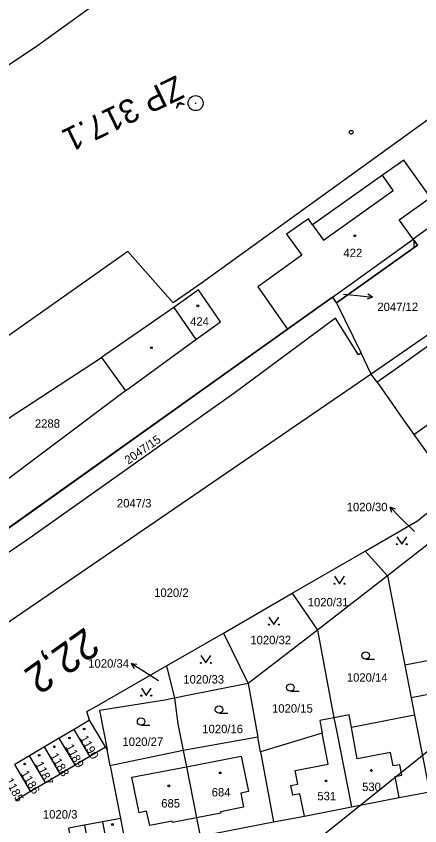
# Model space of a CAD drawing. Extents: x -793666 to -785424, y -1118958 to -1108761.
# Drawn here: x -792219.4 to -792138.1, y -1109916.5 to -1109753.4 of the extents above; entities that cross this region are included whole.
import ezdxf

# ---------------------------------------------------------------- set-up
doc = ezdxf.new("R2010")
doc.units = 0
for name, color, linetype in [('1', 7, 'Continuous'), ('1_2000 - úřady', 7, 'Continuous'), ('Hranice parcel', 7, 'Continuous'), ('Parcelní čísla', 7, 'Continuous'), ('Pop  PČ popisy', 7, 'Continuous'), ('Vnitřní kresba', 7, 'Continuous'), ('Vrstva 44', 7, 'Continuous'), ('Vrstva 53', 7, 'Continuous'), ('Vrstva 63', 7, 'Continuous'), ('Vrstva 7', 7, 'Continuous'), ('Značky budov', 7, 'Continuous'), ('Značky kultur', 7, 'Continuous')]:
    doc.layers.add(name, color=color, linetype=linetype)

msp = doc.modelspace()

# ---------------------------------------------------------------- linework, layer by layer
at = {"layer": '1'}
for q in [(-792262.89, -1109847.12), (-792187.76, -1109811.11)]:
    msp.add_line((-792196.9, -1109800.79), q, dxfattribs=at)
for points in [[(-792036.03, -1109711.9), (-792041.12, -1109704.75), (-792068.33, -1109725.02), (-792101.91, -1109749.26), (-792182.09, -1109807.15)], [(-792182.09, -1109807.15), (-792187.76, -1109811.11)]]:
    msp.add_lwpolyline(points, dxfattribs=at)
msp.add_circle((-792151.91, -1109776.75), 0.375, dxfattribs=at)
at = {"layer": '1_2000 - úřady'}
msp.add_lwpolyline([(-791938.08, -1109742.36), (-792598.01, -1110271.46), (-792786.15, -1110036.8), (-792126.22, -1109507.7)], close=True, dxfattribs=at)
at = {"layer": 'Hranice parcel'}
for p, q in [((-792164.73, -1109816.44), (-792155.68, -1109810)), ((-792155.68, -1109810), (-792154.86, -1109811.14)), ((-792154.86, -1109811.14), (-792149.91, -1109821.24)), ((-792246.55, -1109874.61), (-792164.73, -1109816.44)), ((-792147.85, -1109825.45), (-792149.91, -1109821.24)), ((-792202.2, -1109822.1), (-792197.4, -1109828.81)), ((-792147.85, -1109825.45), (-792244.24, -1109891.34)), ((-792146.7, -1109827.09), (-792147.85, -1109825.45)), ((-792130.85, -1109855.33), (-792144.6, -1109866.13)), ((-792163.8, -1109869.62), (-792149.1, -1109861.11)), ((-792149.1, -1109861.11), (-792144.6, -1109866.13)), ((-792144.6, -1109866.13), (-792158.71, -1109877.05)), ((-792144.6, -1109866.13), (-792141.07, -1109884.12)), ((-792177.65, -1109877.63), (-792163.8, -1109869.62)), ((-792163.8, -1109869.62), (-792158.71, -1109877.05)), ((-792189.12, -1109884.23), (-792177.65, -1109877.63)), ((-792177.65, -1109877.63), (-792172.69, -1109887.78)), ((-792158.71, -1109877.05), (-792172.69, -1109887.78)), ((-792158.71, -1109877.05), (-792155.38, -1109894.7)), ((-792189.12, -1109884.23), (-792187.51, -1109890.76)), ((-792172.69, -1109887.78), (-792170.71, -1109898.62)), ((-792139.11, -1109894.16), (-792136.09, -1109909.62)), ((-792204.62, -1109895.19), (-792207.76, -1109897.06)), ((-792201.42, -1109900.59), (-792204.62, -1109895.19)), ((-792207.76, -1109897.06), (-792210.75, -1109898.83)), ((-792204.56, -1109902.45), (-792207.76, -1109897.06)), ((-792210.75, -1109898.83), (-792213.74, -1109900.59)), ((-792207.56, -1109904.22), (-792210.75, -1109898.83)), ((-792170.71, -1109898.62), (-792185.77, -1109901.33)), ((-792170.17, -1109901.6), (-792170.71, -1109898.62)), ((-792213.74, -1109900.59), (-792216.72, -1109902.36)), ((-792210.54, -1109905.99), (-792213.74, -1109900.59)), ((-792204.56, -1109902.45), (-792201.42, -1109900.59)), ((-792201.11, -1109901.1), (-792201.42, -1109900.59)), ((-792200.48, -1109904.39), (-792201.11, -1109901.1)), ((-792216.72, -1109902.36), (-792219.71, -1109904.13)), ((-792213.53, -1109907.76), (-792216.72, -1109902.36)), ((-792207.56, -1109904.22), (-792204.56, -1109902.45)), ((-792170.17, -1109901.6), (-792167.58, -1109915.69)), ((-792216.52, -1109909.52), (-792219.71, -1109904.13)), ((-792210.54, -1109905.99), (-792207.56, -1109904.22)), ((-792200.48, -1109904.39), (-792198.4, -1109914.97)), ((-792213.53, -1109907.76), (-792210.54, -1109905.99)), ((-792216.52, -1109909.52), (-792213.53, -1109907.76)), ((-792219.5, -1109911.29), (-792216.52, -1109909.52)), ((-792202.02, -1109915.66), (-792205.67, -1109916.35)), ((-792198.4, -1109914.97), (-792202.02, -1109915.66)), ((-792202.02, -1109915.66), (-792200.79, -1109922.09)), ((-792198.4, -1109914.97), (-792197.14, -1109921.4)), ((-792182.33, -1109918.59), (-792167.58, -1109915.69)), ((-792205.67, -1109916.35), (-792204.45, -1109922.79))]:
    msp.add_line(p, q, dxfattribs=at)
for points in [[(-792226.53, -1109766.83), (-792215.1, -1109759.26), (-792190.07, -1109741.13), (-792187.8, -1109739.49), (-792182.21, -1109735.57)], [(-792088.89, -1109762.3), (-792112.22, -1109778.74), (-792129.24, -1109790.96), (-792130.77, -1109792.06), (-792139.4, -1109798.31)], [(-792139.4, -1109798.31), (-792142.25, -1109794.38), (-792135.9, -1109789.9), (-792141.29, -1109782.35), (-792145.59, -1109785.4), (-792159.68, -1109795.39), (-792160.54, -1109794.19), (-792164.93, -1109797.25), (-792161.84, -1109801.51), (-792170.75, -1109807.89), (-792164.73, -1109816.44)], [(-792155.68, -1109810), (-792151.63, -1109807.06), (-792139.68, -1109798.51), (-792139.4, -1109798.31)], [(-792154.86, -1109811.14), (-792138.54, -1109799.49), (-792139.4, -1109798.31)], [(-792119.78, -1109808.18), (-792120.9, -1109806.8), (-792147.85, -1109825.45)], [(-792197.4, -1109828.81), (-792183.19, -1109818.5), (-792178.27, -1109814.93), (-792182.67, -1109808.46), (-792187.68, -1109812.04), (-792202.2, -1109822.1)], [(-792121.37, -1109809.32), (-792125.81, -1109812.22), (-792143.12, -1109824.61), (-792146.7, -1109827.09)], [(-792149.91, -1109821.24), (-792150.43, -1109821.57), (-792155.08, -1109814.18), (-792175.53, -1109829.37), (-792217.28, -1109858.93), (-792231.29, -1109868.36), (-792246.55, -1109874.61)], [(-792197.4, -1109828.81), (-792224.99, -1109849.52), (-792231.36, -1109841.16), (-792202.2, -1109822.1)], [(-792146.7, -1109827.09), (-792143.74, -1109831.31), (-792142.22, -1109833.47), (-792139.27, -1109837.66), (-792132.41, -1109847.24), (-792127.98, -1109853)], [(-792149.1, -1109861.11), (-792138.53, -1109855), (-792136.75, -1109853.52), (-792131.07, -1109855.27), (-792130.85, -1109855.33)], [(-792125.37, -1109880.3), (-792130.03, -1109881.49), (-792129.95, -1109881.94), (-792141.07, -1109884.12)], [(-792204.62, -1109895.19), (-792205.19, -1109893.47), (-792203.27, -1109892.37), (-792189.12, -1109884.23)], [(-792141.07, -1109884.12), (-792139.79, -1109890.67), (-792139.11, -1109894.16)], [(-792172.69, -1109887.78), (-792185.54, -1109890.37), (-792187.51, -1109890.76)], [(-792187.51, -1109890.76), (-792189.46, -1109891.15), (-792202.65, -1109893.23), (-792201.11, -1109901.1)], [(-792187.51, -1109890.76), (-792186.82, -1109895.94), (-792185.77, -1109901.33)], [(-792139.11, -1109894.16), (-792151.86, -1109896.66), (-792152.34, -1109894.11), (-792155.38, -1109894.7)], [(-792155.38, -1109894.7), (-792158.21, -1109895.25), (-792157.72, -1109897.8), (-792170.17, -1109901.6)], [(-792155.38, -1109894.7), (-792154.89, -1109897.3), (-792151.83, -1109912.63)], [(-792185.77, -1109901.33), (-792197.65, -1109903.78), (-792200.21, -1109904.33), (-792200.48, -1109904.39)], [(-792185.77, -1109901.33), (-792185.12, -1109904.56), (-792183.07, -1109914.88), (-792182.33, -1109918.59)], [(-792151.83, -1109912.63), (-792142.25, -1109910.79), (-792136.09, -1109909.62)], [(-792167.58, -1109915.69), (-792161.31, -1109914.51), (-792151.83, -1109912.63)], [(-792205.67, -1109916.35), (-792208.89, -1109916.96), (-792207.73, -1109923.09)]]:
    msp.add_lwpolyline(points, dxfattribs=at)
at = {"layer": 'Pop  PČ popisy'}
for p, q in [((-792153.46, -1109809.36), (-792150.62, -1109809.64)), ((-792150.62, -1109809.64), (-792147.64, -1109809.95)), ((-792147.64, -1109809.95), (-792148.58, -1109809.35)), ((-792147.64, -1109809.95), (-792148.68, -1109810.35)), ((-792142, -1109854.36), (-792144.12, -1109852.24)), ((-792144.12, -1109852.24), (-792143.06, -1109852.59)), ((-792144.12, -1109852.24), (-792143.77, -1109853.3)), ((-792139.15, -1109857.21), (-792142, -1109854.36)), ((-792193.69, -1109885.38), (-792196.23, -1109883.79)), ((-792196.23, -1109883.79), (-792195.12, -1109883.9)), ((-792196.23, -1109883.79), (-792195.65, -1109884.75)), ((-792190.75, -1109887.24), (-792193.69, -1109885.38))]:
    msp.add_line(p, q, dxfattribs=at)
at = {"layer": 'Vnitřní kresba'}
for p, q in [((-792143.42, -1109788.47), (-792145.59, -1109785.4)), ((-792157.49, -1109798.49), (-792143.42, -1109788.47)), ((-792159.68, -1109795.39), (-792157.49, -1109798.49)), ((-792187.68, -1109812.04), (-792183.19, -1109818.5)), ((-792139.27, -1109837.66), (-792135.56, -1109835)), ((-792132.94, -1109889.33), (-792139.79, -1109890.67)), ((-792156.52, -1109904.06), (-792157.72, -1109897.8)), ((-792150.67, -1109902.98), (-792151.86, -1109896.66)), ((-792185.12, -1109904.56), (-792174.06, -1109902.44)), ((-792174.06, -1109902.44), (-792172.6, -1109909.57)), ((-792143.96, -1109901.68), (-792150.67, -1109902.98)), ((-792143.45, -1109904.41), (-792143.96, -1109901.68)), ((-792163.2, -1109905.35), (-792156.52, -1109904.06)), ((-792142.11, -1109904.16), (-792143.45, -1109904.41)), ((-792141.71, -1109906.3), (-792142.11, -1109904.16)), ((-792196.12, -1109906.67), (-792185.12, -1109904.56)), ((-792162.64, -1109908.05), (-792163.2, -1109905.35)), ((-792194.65, -1109913.84), (-792196.12, -1109906.67)), ((-792143.05, -1109906.55), (-792141.71, -1109906.3)), ((-792142.25, -1109910.79), (-792143.05, -1109906.55)), ((-792164.07, -1109908.34), (-792162.64, -1109908.05)), ((-792163.67, -1109910.29), (-792164.07, -1109908.34)), ((-792172.6, -1109909.57), (-792174.15, -1109909.89)), ((-792174.15, -1109909.89), (-792173.64, -1109912.74)), ((-792162.24, -1109910), (-792163.67, -1109910.29)), ((-792161.31, -1109914.51), (-792162.24, -1109910)), ((-792193.15, -1109913.53), (-792194.65, -1109913.84)), ((-792192.52, -1109916.41), (-792193.15, -1109913.53)), ((-792178.17, -1109913.93), (-792183.07, -1109914.88)), ((-792173.64, -1109912.74), (-792178.22, -1109913.63)), ((-792178.22, -1109913.63), (-792178.17, -1109913.93)), ((-792187.99, -1109915.53), (-792192.52, -1109916.41)), ((-792187.94, -1109915.82), (-792187.99, -1109915.53)), ((-792183.07, -1109914.88), (-792187.94, -1109915.82))]:
    msp.add_line(p, q, dxfattribs=at)
at = {"layer": 'Vrstva 44'}
msp.add_line((-792139.2, -1109799.96), (-792139.2, -1109798.58), dxfattribs=at)
at = {"layer": 'Vrstva 53'}
for points in [[(-792226.53, -1109766.83), (-792215.1, -1109759.26), (-792190.07, -1109741.13), (-792187.8, -1109739.49), (-792182.21, -1109735.57), (-792171.12, -1109727.8), (-792158.73, -1109719.12), (-792137.25, -1109704.07), (-792130.48, -1109712.65), (-792129.14, -1109711.27), (-792119.15, -1109724.06), (-792100.25, -1109709.81), (-792096.91, -1109714.15), (-792092.06, -1109710.49), (-792095.42, -1109706.17), (-792092.71, -1109704.13), (-792082.74, -1109715.97), (-792057.33, -1109700.37), (-792051.73, -1109696.36), (-792038.26, -1109686.52)], [(-792099.3, -1109747.92), (-792088.89, -1109762.3), (-792112.22, -1109778.74), (-792129.24, -1109790.96), (-792130.77, -1109792.06), (-792139.4, -1109798.31), (-792138.54, -1109799.49), (-792154.86, -1109811.14), (-792155.68, -1109810), (-792164.73, -1109816.44), (-792246.55, -1109874.61)]]:
    msp.add_lwpolyline(points, dxfattribs=at)
msp.add_lwpolyline([(-792182.67, -1109808.46), (-792187.68, -1109812.04), (-792202.2, -1109822.1), (-792197.4, -1109828.81), (-792183.19, -1109818.5), (-792178.27, -1109814.93)], close=True, dxfattribs=at)
at = {"layer": 'Vrstva 63'}
msp.add_line((-792183.36, -1109770.88), (-792183.16, -1109770.88), dxfattribs=at)
msp.add_circle((-792183.26, -1109770.88), 1.51, dxfattribs=at)
at = {"layer": 'Značky budov'}
for centre in [(-792151.16, -1109797.6), (-792182.82, -1109811.71), (-792192.16, -1109820.14), (-792205.73, -1109896.96), (-792208.7, -1109898.79), (-792211.73, -1109900.54), (-792214.78, -1109902.28), (-792217.71, -1109904.02), (-792178.29, -1109905.81), (-792147.84, -1109905.33), (-792156.99, -1109907.42), (-792188.66, -1109908.42), (-792200.03, -1109916.21)]:
    msp.add_circle(centre, 0.175, dxfattribs=at)
at = {"layer": 'Značky kultur'}
for p, q in [((-792148.98, -1109882.92), (-792147.23, -1109882.92)), ((-792164.16, -1109889.35), (-792162.41, -1109889.35)), ((-792178.54, -1109893.8), (-792176.79, -1109893.8)), ((-792194.25, -1109896.2), (-792192.5, -1109896.2))]:
    msp.add_line(p, q, dxfattribs=at)
for points in [[(-792142.72, -1109858.25), (-792141.72, -1109859.75), (-792140.72, -1109858.25)], [(-792155.24, -1109866.21), (-792154.24, -1109867.71), (-792153.24, -1109866.21)], [(-792168.51, -1109874.43), (-792167.51, -1109875.93), (-792166.51, -1109874.43)], [(-792182.2, -1109882.15), (-792181.2, -1109883.65), (-792180.2, -1109882.15)], [(-792194.2, -1109888.75), (-792193.2, -1109890.25), (-792192.2, -1109888.75)]]:
    msp.add_lwpolyline(points, dxfattribs=at)
for centre, radius in [((-792142.72, -1109859.75), 0.1), ((-792140.72, -1109859.75), 0.1), ((-792155.24, -1109867.71), 0.1), ((-792153.24, -1109867.71), 0.1), ((-792168.51, -1109875.93), 0.1), ((-792166.51, -1109875.93), 0.1), ((-792148.98, -1109882.17), 0.75), ((-792182.2, -1109883.65), 0.1), ((-792180.2, -1109883.65), 0.1), ((-792164.16, -1109888.6), 0.75), ((-792194.2, -1109890.25), 0.1), ((-792192.2, -1109890.25), 0.1), ((-792178.54, -1109893.05), 0.75), ((-792194.25, -1109895.45), 0.75)]:
    msp.add_circle(centre, radius, dxfattribs=at)

# ---------------------------------------------------------------- texts
at = {"layer": 'Parcelní čísla'}
for s, p in [('422', (-792153.47, -1109801.9)), ('2047/12', (-792146.63, -1109812.77)), ('424', (-792184.38, -1109815.72)), ('2288', (-792215.65, -1109836.27)), ('2047/3', (-792199.12, -1109852.33)), ('1020/30', (-792152.8, -1109853.09)), ('1020/2', (-792191.62, -1109870.35)), ('1020/31', (-792160.66, -1109872.27)), ('1020/32', (-792172.23, -1109879.89)), ('1020/34', (-792204.9, -1109884.62)), ('1020/33', (-792185.74, -1109887.81)), ('1020/14', (-792152.79, -1109887.44)), ('1020/15', (-792167.86, -1109893.68)), ('1020/16', (-792181.92, -1109897.81)), ('1020/27', (-792198.01, -1109900.38)), ('684', (-792180.02, -1109910.56)), ('530', (-792149.7, -1109909.47)), ('531', (-792158.72, -1109911.33)), ('685', (-792190.19, -1109912.79)), ('1020/3', (-792214.04, -1109915.01))]:
    msp.add_text(s, height=1.7, dxfattribs=at).set_placement(p)
for s, rotation, p in [('2047/15', 35, (-792196.83, -1109843.73)), ('1190', 299, (-792206.63, -1109898.81)), ('1189', 298, (-792209.54, -1109900.52)), ('1188', 300, (-792212.64, -1109902.36)), ('1187', 297, (-792215.66, -1109904.01)), ('1186', 301, (-792218.59, -1109905.93)), ('1185', 298, (-792221.71, -1109907.37))]:
    msp.add_text(s, height=1.7, rotation=rotation, dxfattribs=at).set_placement(p)
at = {"layer": 'Vrstva 63'}
msp.add_text('ŽP 317.1', height=4.8, rotation=205.85, dxfattribs=at).set_placement((-792187.13, -1109765.19))
at = {"layer": 'Vrstva 7'}
msp.add_text('22,2', height=6, rotation=215.4652, dxfattribs=at).set_placement((-792205.52, -1109876.32))

doc.saveas('drawing.dxf')
